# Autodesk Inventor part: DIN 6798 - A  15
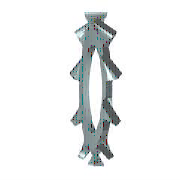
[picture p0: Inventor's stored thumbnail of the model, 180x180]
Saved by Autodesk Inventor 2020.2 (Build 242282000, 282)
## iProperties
Manager: www.cadconsulting.pl
Company: Fabian Stasiak CAD Consulting
Created: 2006-02
Part Number: DIN 6798 - A  15
Material: Stal, miękka
Description: Podkładka
Document SubType Name: Modeling
Standard: DIN 6798
Designer: F.Stasiak
Standards Organization: DIN
Language: pl-PL
Size Designation: A  15
Categories: <MemberInstance><Categories><Category DisplayName="Mocowania" InternalName="e4da775c-781d-43d5-af7c-5136215cf5a6" Mnemonic="FSTN"><Category DisplayName="Podkład
Density: 1 g/cm^3
Appearance: Stal
Author: F.Stasiak
Subject: Zbiór ćwiczeń. Autodesk Inventor 2020. Kurs podstawowy
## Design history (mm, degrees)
node "Bryła1"
node "Korpusy bryłowe"
node "Korpusy powierzchniowe"
sketch "Szkic1"
  geometry: C1 r 12 at (0, 0); C2 r 7.5 at (0, 0); 1 further point
  constraints: 2 centre point, 2 coincident
  dimensions: "d0" = 15 diameter of C2 (= SD1); "d1" = 24 diameter of C1 (= SD2)
extrude "Bryła" new body sketch "Szkic1" distance "d2" = 1 (= SD); taper "d3" = 0 deg
sketch "Szkic2"
  geometry: L1 (-1.046, 11.954)-(-0.85, 9.713); L2 (0, 12)-(0, 0); L3 (-0.85, 9.713)-(0, 0); L4 (1.046, 11.954)-(0.85, 9.713); L5 (0.85, 9.713)-(0, 0); A1 r 12 centre (0, 0) between (-1.046, 11.954) and (0, 12) reference; A2 r 9.75 centre (0, 0) between (0.85, 9.713) and (-0.85, 9.713)
  constraints: 10 end point, 5 point on circle, 2 symmetric about line, 1 centre point, 1 coincident, 1 collinear, 1 vertical, 2 other
  dimensions: "d4" = 19.5 diameter of A2 (= 0.5 x SD2 + 0.5 x SD1); "d5" = 5 deg angle of L2 L1 (computed from SAZ)
extrude "Wycięcie" cut sketch "Szkic2" extent not by distance; stored distance "d6" = 1 (= SD); taper "d7" = 0 deg
fillet "Zaokrąglenie1" dims "d8" = 0.36 (= 0.015 x SD2)
pattern_circular "Wycięcia" dims angle "d11" = 360 deg
workaxis "Work Axis2"
workplane "Work Plane1"
other parameters: "SD1" = 15 [user parameter; used in 2 equation terms], "SD2" = 24 [user parameter; used in 3 equation terms], "SD" = 1 [user parameter; used in 2 equation terms], "d13" = 0, "d16" = 0, "d17" = 0, "d18" = 0, "NND" = 14 [user parameter]
